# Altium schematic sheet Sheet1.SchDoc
size A; SheetNumber: 1; SheetTotal: 1
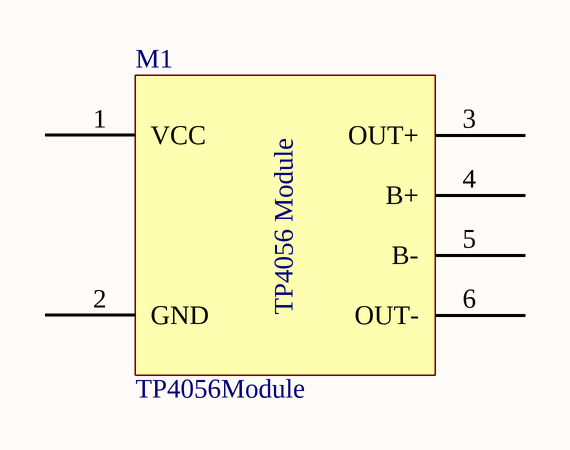
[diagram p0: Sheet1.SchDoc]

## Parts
M1  TP4056Module  [TP4056Module]

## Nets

Not connected (* = marked no-connect by the designer): M1 1(VCC) 2(GND) 3(OUT+) 4(B+) 5(B-) 6(OUT-)

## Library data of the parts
M1 = TP4056Module: TP4056 Module for managing battery charging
